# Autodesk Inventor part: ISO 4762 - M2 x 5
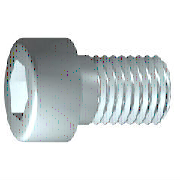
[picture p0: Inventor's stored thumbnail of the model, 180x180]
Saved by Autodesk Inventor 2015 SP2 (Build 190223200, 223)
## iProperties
Created: 2014-02
Part Number: ISO 4762 - M2 x 5
Material: Edelstahl, 440C
Description: Innensechskantschraube
Document SubType Name: Modeling
Standard: ISO 4762
Designer: ryll
Standard Revision: 1998
Standards Organization: DIN
Language: de-DE
Size Designation: M2 x 5
Categories: <MemberInstance><Categories><Category DisplayName="Verbindungselemente" InternalName="e4da775c-781d-43d5-af7c-5136215cf5a6" Mnemonic="FSTN"><Category DisplayNam
Density: 7.75 g/cm^3
Appearance: Halbpoliert
IsCustomPart: 0
Author: ryll
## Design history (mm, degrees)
sketch "Skizze1"
  geometry: L1 (-0.5, 0)-(5, 0); L2 (5, 0)-(5, 1); L3 (5, 1)-(1, 1); L4 (1, 1)-(0.755, 1); L5 (0.755, 1)-(0, 1); L6 (0, 1)-(0, 1.9); L7 (0, 1.9)-(-2, 1.9); L8 (-2, 1.9)-(-2, 0.866); L9 (-2, 0.866)-(-1, 0.866); L10 (-1, 0.866)-(-0.5, 0); L11 (-3.4, 0)-(6.4, 0) reference; L12 (0, -0.38)-(0, 2.28) reference; L13 (1, 1)-(0, 1)
  constraints: 22 end point, 6 parallel, 2 collinear, 2 perpendicular, 1 horizontal, 1 point on line
  dimensions: "d1" = 4 distance from line of L3.end L2 (= GEL); "d2" = 0.24548 distance of L4.end L3.end (computed from GAL); "d3" = 2 distance between parallel lines of L8 L6 (= KOH); "d4" = 1 distance of L8.end L9.end (= INTI); "d5" = 60 deg angle of L10 L1; "d6" = 2 diameter of L3 L1 (= GD); "d7" = 2 diameter of L5 L1 (= BDM); "d8" = 1.73205 diameter of L9 L1 (= 1.1547 x SW); "d9" = 3.8 diameter of L7 L1 (= KOD); "d26" = 5 distance between parallel lines of L12 L2 (= NLG)
revolve "Körper" sketch "Skizze1" stored, may be unused: angle "d10" = 90 deg
sketch "Skizze2"
  geometry: L1 (0, -2.66)-(0, 2.66) reference; L2 (-2.66, 0)-(2.66, 0) reference; L3 (0.866, 0)-(0.433, -0.75); L4 (0.433, -0.75)-(-0.433, -0.75); L5 (-0.433, -0.75)-(-0.866, 0); L6 (-0.866, 0)-(-0.433, 0.75); L7 (-0.433, 0.75)-(0.433, 0.75); L8 (0.433, 0.75)-(0.866, 0); 2 further points
  constraints: 12 end point, 1 coincident, 1 horizontal alignment, 1 point on line, 12 other
extrude "Loch" join sketch "Skizze2" stored distance "d11" = 10; taper "d12" = 0 deg
workplane "Work Plane1"
fillet "Fillet2" dims "d30" = 0.1 (= R)
body "Solid1"
fillet "Rundung1" dims "d17" = 0.2 (= RR)
feature "Gewinde" dims "d13" = 4 (= GEL), "d14" = 0
chamfer "Fase1" distance "d15" = 0.24538 (= -0.5 x SPD + 0.5 x GD); stored, may be unused: second distance "d16" = 0.24538 (= GUL), angle "d27" = 45 deg
other parameters: "GD" = 2 [user parameter; used in 2 equation terms], "NLG" = 5 [user parameter; used in 1 equation term], "GEL" = 4 [user parameter; used in 2 equation terms], "KOD" = 3.8 [user parameter; used in 1 equation term], "KOH" = 2 [user parameter; used in 1 equation term], "INTI" = 1 [user parameter; used in 1 equation term], "GAL" = 0.24538 (= 0.61345 x PTC) [user parameter; used in 1 equation term], "GUL" = 0.24538 (= 0.61345 x PTC) [user parameter; used in 1 equation term], "BDM" = 2 (= NND) [user parameter; used in 1 equation term], "SW" = 1.5 [user parameter; used in 2 equation terms], "RR" = 0.2 [user parameter; used in 1 equation term], "SPD" = 1.50924 (= NND - 1.2269 x PTC) [user parameter; used in 1 equation term], "d19" = 0, "d28" = 0, "d29" = 0, "R" = 0.1 [user parameter; used in 1 equation term], "TOA" = 30 deg [user parameter], "GD1" = 1.50924 (= THREADDIA - 1.2269 x PTC) [user parameter], "THREADDIA" = 2 [user parameter; used in 1 equation term], "FAWI" = 45 deg [user parameter], "TPU" = 25 (computed from PTC) [user parameter], "PTC" = 0.4 [user parameter; used in 5 equation terms], "NND" = 2 [user parameter; used in 2 equation terms], "E0" = 1.7325 (= 1.155 x SW) [user parameter]
